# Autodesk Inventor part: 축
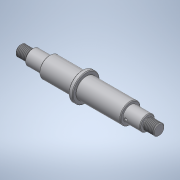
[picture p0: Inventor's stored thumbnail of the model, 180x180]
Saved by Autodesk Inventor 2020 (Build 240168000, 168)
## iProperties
CustomPartVersion: 1
Created: 2021-06
Part Number: 축
Material: 강철, 연강
Document SubType Name: Modeling
Designer: mdu
Density: 1 g/cm^3
Appearance: 흰색
Author: mdu
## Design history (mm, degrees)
sketch "주 스케치"
  geometry: L1 (0, 0)-(203, 0) reference; L2 (0, 0)-(0, 8); L3 (0, 8)-(17, 8); L4 (17, 8)-(17, 11); L5 (17, 11)-(42, 11); L6 (42, 11)-(42, 15); L7 (42, 15)-(90, 15); L8 (90, 15)-(90, 20); L9 (96, 20)-(96, 15); L10 (90, 20)-(96, 20); L11 (161, 15)-(161, 11); L12 (96, 15)-(161, 15); L13 (186, 11)-(186, 8); L14 (161, 11)-(186, 11); L15 (203, 8)-(203, 0); L16 (186, 8)-(203, 8)
  constraints: 32 end point, 9 horizontal, 8 vertical
  dimensions: "d3" = 16 diameter of L3 L1 (derived); "d4" = 22 diameter of L5 L1 (derived); "d5" = 30 diameter of L7 L1 (derived); "d6" = 40 diameter of L10 L1 (derived); "d7" = 30 diameter of L12 L1 (derived); "d8" = 22 diameter of L14 L1 (derived); "d9" = 16 diameter of L16 L1 (derived)
revolve "회전1" sketch "주 스케치" stored, may be unused: angle "d10" = 0 deg
chamfer "모따기1" distance "d11" = 1; stored, may be unused: second distance "d12" = 1, angle "d13" = 45 deg
chamfer "모따기2" distance "d14" = 1; stored, may be unused: second distance "d15" = 1, angle "d16" = 45 deg
node "키홈1"
chamfer "모따기3" distance "d17" = 1; stored, may be unused: second distance "d18" = 1, angle "d19" = 45 deg
fillet "모깎기1" dims "d20" = 0.3
chamfer "모따기4" distance "d21" = 1; stored, may be unused: second distance "d22" = 1, angle "d23" = 45 deg
chamfer "모따기5" distance "d24" = 1; stored, may be unused: second distance "d25" = 1, angle "d26" = 45 deg
fillet "모깎기2" dims "d27" = 0.3
chamfer "모따기6" distance "d28" = 1; stored, may be unused: second distance "d29" = 1, angle "d30" = 45 deg
chamfer "모따기7" distance "d31" = 1; stored, may be unused: second distance "d32" = 1, angle "d33" = 45 deg
node "키홈2"
chamfer "모따기8" distance "d34" = 1; stored, may be unused: second distance "d35" = 1, angle "d36" = 45 deg
sketch "스케치3"
  geometry: L1 (1, 8)-(17, 8) reference; L2 (17, -10)-(17, 10) reference; L3 (186, 10)-(186, -10) reference; L4 (186, 8)-(202, 8) reference; L5 (203, 7)-(203, -7) reference; L6 (0, 0)-(203, 0); L7 (17, 8)-(15.5, 8); L8 (15.5, 8)-(15.5, 7); L9 (15.5, 7)-(17, 7); L10 (17, 7)-(17, 8); L11 (186, 8)-(187.5, 8); L12 (187.5, 8)-(187.5, 7); L13 (187.5, 7)-(186, 7); L14 (186, 7)-(186, 8)
  constraints: 18 end point, 4 parallel, 2 horizontal, 2 perpendicular, 1 midpoint
  dimensions: "d37" = 14 diameter of L13 L6; "d39" = 1.5 distance of L12.end L13.end; "d40" = 14 diameter of L9 L6; "d41" = 1.5 distance of L8.end L9.end
revolve "회전2" sketch "스케치3" stored, may be unused: angle "d42" = 90 deg
feature "스레드1" dims "d43" = 10, "d44" = 0
feature "스레드2" dims "d45" = 10, "d46" = 0
sketch "스케치4"
  geometry: L1 (186, 7)-(186, -7) reference; L2 (186, 10)-(186, -10) reference; L3 (161, -11)-(185, -11) reference; L4 (165, -11)-(165, -9); L5 (165, -9)-(167, -11); L6 (165, -11)-(167, -11); 1 further point
  constraints: 6 end point, 2 point on line, 1 collinear, 1 perpendicular
  dimensions: "d47" = 21 distance from line of L2 L4.start; "d48" = 4 diameter of L5.end L4; "d49" = 45 deg angle of L4 L5
revolve "회전3" sketch "스케치4" stored, may be unused: angle "d50" = 90 deg
node "솔리드1"
feature "iFeature3:1"
feature "iFeature3:2"
node "투영된 루프1"
other parameters: "d0" = 0, "d1" = 0, "d2" = 0
